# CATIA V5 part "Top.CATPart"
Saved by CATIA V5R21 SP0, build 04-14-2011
Part number: Top
Bounding box of the stored display mesh (mm): x -92.8 to 92.8, y 0 to 102.089, z 0 to 2.8
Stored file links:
  C:\Users\Pouria\Desktop\Box\Assembled\Top.CATPart
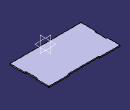
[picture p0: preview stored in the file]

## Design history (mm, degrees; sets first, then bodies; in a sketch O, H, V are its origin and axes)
Body1 (main body)
  Sketch1 on xy-plane, origin (0, 0, 0), H (1, 0, 0), V (0, 1, 0)
    point P1 (-92.8, 0)
    line L1 (-92.8, 0) -> (92.8, 0)
    line L2 (92.8, 0) -> (92.8, 39.289)
    line L3 (92.8, 102.089) -> (40, 102.089)
    line L4 (-92.8, 102.089) -> (-92.8, 69.289)
    point P2 (92.8, 0)
    point P3 (92.8, 102.089)
    point P5 (92.8, 69.289)
    line L5 (92.8, 69.289) -> (90, 69.289)
    line L6 (90, 69.289) -> (90, 39.289)
    line L7 (90, 39.289) -> (92.8, 39.289)
    line L8 (-92.8, 69.289) -> (-90, 69.289)
    line L9 (-90, 69.289) -> (-90, 39.289)
    line L10 (-90, 39.289) -> (-92.8, 39.289)
    point P12 (-92.8, 39.289)
    point P13 (-40, 102.089)
    line L11 (-40, 102.089) -> (-40, 99.289)
    line L12 (-40, 99.289) -> (40, 99.289)
    line L13 (40, 99.289) -> (40, 102.089)
    line L14 (92.8, 69.289) -> (92.8, 102.089)
    line L15 (-40, 102.089) -> (-92.8, 102.089)
    line L16 (-92.8, 39.289) -> (-92.8, 0)
    length L1 = 185.6
    distance L6 L2 = 2.8
    distance L9 L4 = 2.8
    distance L5 L3 = 32.8
    distance L8 L3 = 32.8
    length L6 = 30
    length L9 = 30
    length L12 = 80
    length L13 = 2.8
    distance P2 P3 = 102.089
    coincidence: P1 H, P5 L2, P12 L4, P13 L3, L2 L14, L3 L15, L4 L16
    horizontal: L1 H, L3 H, L5 H, L7 H, L8 H, L10 H, L12 H, L15 H
    vertical: L2 V, L4 V, L6 V, L9 V, L11 V, L13 V, L14 V, L16 V
    symmetry: L2 L4 V, L13 L11 V
  Pad1: profile Sketch1, direction (0, 0, 1), length 2.8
